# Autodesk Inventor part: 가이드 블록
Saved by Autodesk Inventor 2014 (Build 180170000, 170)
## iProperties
Created: 2026-09
Part Number: 가이드 블록
Material: 일반
Document SubType Name: Modeling
Designer: dg
Density: 1 g/cm^3
Appearance: 기본값
Author: dg
Author: jhkim
Creation Date: 2026-08-26
Sending System: Autodesk Inventor 2027
Preprocessor: ST-DEVELOPER v20.1
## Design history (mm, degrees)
node "가이드 블록1"
node "솔리드1"
node "기준1"
